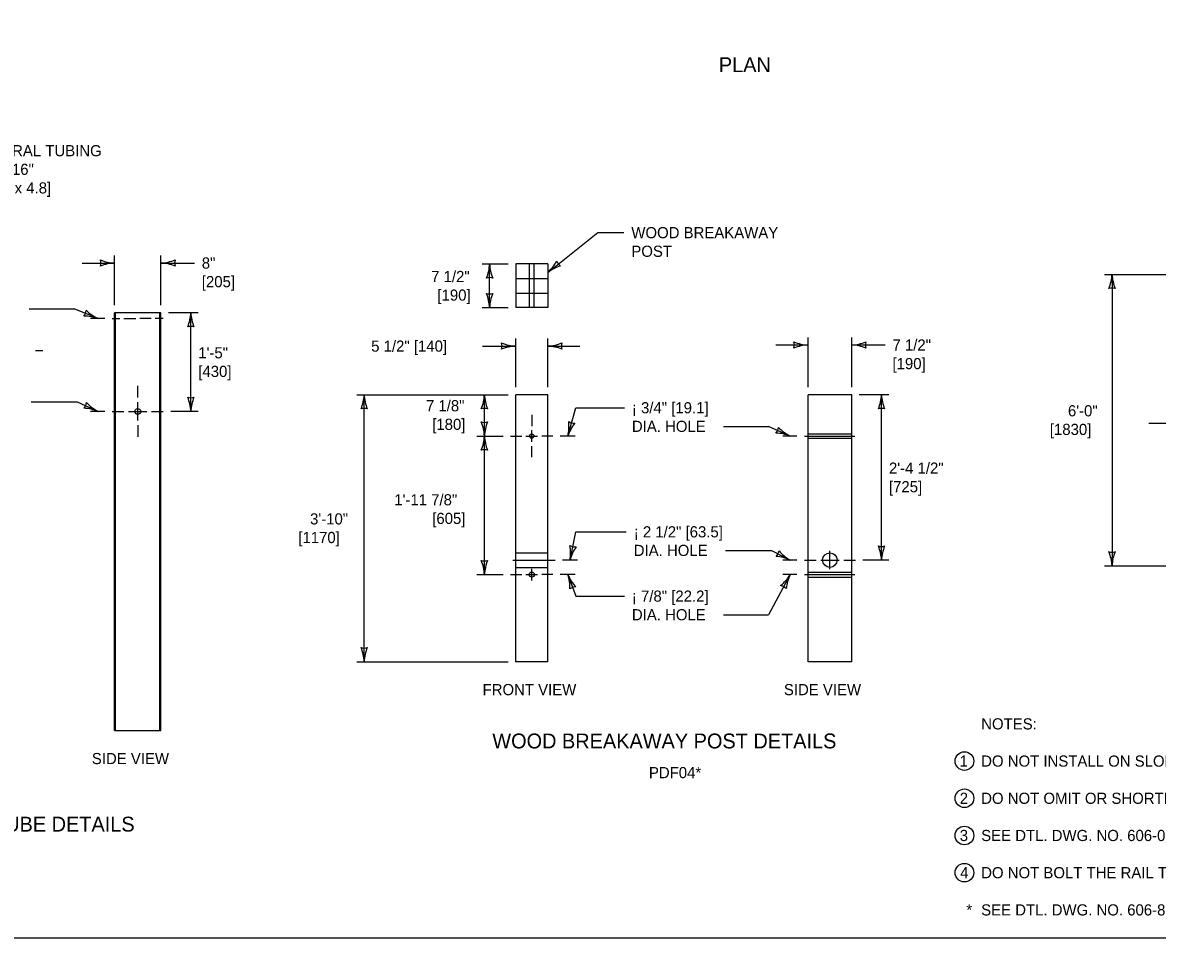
# Model space of a CAD drawing. Extents: x 49991.4 to 50021, y 49987.6 to 50011.4.
# Drawn here: x 50001.79 to 50007.89, y 49987.8 to 49992.72 of the extents above; entities that cross this region are included whole.
import ezdxf

# ---------------------------------------------------------------- set-up
doc = ezdxf.new("R2010")
doc.units = 0
for name, color, linetype in [('Level 1', 7, 'Continuous'), ('Level 2', 7, 'Continuous'), ('Level 3', 7, 'Continuous'), ('Level 4', 7, 'Continuous'), ('Level 5', 7, 'Continuous')]:
    doc.layers.add(name, color=color, linetype=linetype)

msp = doc.modelspace()

# ---------------------------------------------------------------- linework, layer by layer
at = {"layer": 'Level 1'}
for p, q in [((50004.4396, 49991.4237), (50004.4396, 49991.1893)), ((50004.6112, 49991.4237), (50004.4396, 49991.4237)), ((50004.6112, 49991.4237), (50004.6112, 49991.1893)), ((50002.284, 49988.9152), (50002.284, 49991.1616)), ((50002.5336, 49991.1616), (50002.284, 49991.1616)), ((50002.5336, 49988.9152), (50002.5336, 49991.1616)), ((50004.6112, 49991.1893), (50004.4396, 49991.1893)), ((50001.8587, 49990.9595), (50001.8987, 49990.9595)), ((50004.4396, 49989.2858), (50004.4396, 49990.721)), ((50004.6112, 49990.721), (50004.4396, 49990.721)), ((50004.6112, 49989.2858), (50004.6112, 49990.721)), ((50006.0102, 49989.2858), (50006.0102, 49990.721)), ((50006.2446, 49990.721), (50006.0102, 49990.721)), ((50006.2446, 49989.2858), (50006.2446, 49990.721)), ((50007.8408, 49990.5679), (50008.6722, 49990.5679)), ((50004.6112, 49989.2858), (50004.4396, 49989.2858)), ((50006.2446, 49989.2858), (50006.0102, 49989.2858)), ((50002.284, 49988.9152), (50002.5336, 49988.9152))]:
    msp.add_line(p, q, dxfattribs=at)
msp.add_lwpolyline([(49999.3835, 49998.9992), (50016.7501, 49998.9992), (50016.7501, 49987.7988), (49999.3835, 49987.7988)], close=True, dxfattribs=at)
for centre, radius in [((50002.4088, 49990.6312), 0.0156), ((50004.5254, 49990.4987), 0.0117), ((50006.1274, 49989.8318), 0.039), ((50004.5254, 49989.7538), 0.0136)]:
    msp.add_circle(centre, radius, dxfattribs=at)
at = {"layer": 'Level 2'}
for centre in [(50006.8505, 49988.7516), (50006.8505, 49988.5516), (50006.8505, 49988.3516), (50006.8505, 49988.1516)]:
    msp.add_circle(centre, 0.05, dxfattribs=at)
at = {"layer": 'Level 3'}
for p, q in [((50004.6112, 49991.3778), (50004.8814, 49991.5921)), ((50004.8814, 49991.5921), (50005.0208, 49991.5921)), ((50002.284, 49991.2016), (50002.284, 49991.4688)), ((50002.5336, 49991.2016), (50002.5336, 49991.4688)), ((50002.1106, 49991.4288), (50002.284, 49991.4288)), ((50002.5336, 49991.4288), (50002.7128, 49991.4288)), ((50004.2592, 49991.4237), (50004.3996, 49991.4237)), ((50004.2992, 49991.1893), (50004.2992, 49991.4237)), ((50007.6036, 49991.3678), (50008.6322, 49991.3678)), ((50007.6436, 49991.3678), (50007.6436, 49989.8012)), ((50001.8257, 49991.1826), (50002.0669, 49991.1826)), ((50002.1954, 49991.1304), (50002.0669, 49991.1826)), ((50002.2317, 49991.1304), (50002.1554, 49991.1304)), ((50002.734, 49991.1616), (50002.5736, 49991.1616)), ((50002.694, 49990.6312), (50002.694, 49991.1616)), ((50004.2592, 49991.1893), (50004.3996, 49991.1893)), ((50004.4396, 49990.761), (50004.4396, 49991.0223)), ((50004.6112, 49990.761), (50004.6112, 49991.0223)), ((50006.0102, 49990.761), (50006.0102, 49991.0282)), ((50006.2446, 49990.761), (50006.2446, 49991.0282)), ((50004.2614, 49990.9823), (50004.4396, 49990.9823)), ((50004.6112, 49990.9823), (50004.7847, 49990.9823)), ((50005.8368, 49990.9882), (50006.0102, 49990.9882)), ((50006.2446, 49990.9882), (50006.4238, 49990.9882)), ((50003.5853, 49990.721), (50004.3996, 49990.721)), ((50003.6253, 49989.2858), (50003.6253, 49990.721)), ((50004.2713, 49990.4987), (50004.2713, 49990.721)), ((50006.4449, 49990.721), (50006.2846, 49990.721)), ((50006.4049, 49989.8318), (50006.4049, 49990.721)), ((50004.7194, 49990.4987), (50004.763, 49990.6509)), ((50004.763, 49990.6509), (50005.0237, 49990.6509)), ((50002.2317, 49990.6312), (50002.1555, 49990.6312)), ((50002.734, 49990.6312), (50002.586, 49990.6312)), ((50005.5563, 49990.5509), (50005.7974, 49990.5509)), ((50005.914, 49990.4987), (50005.7974, 49990.5509)), ((50004.2313, 49990.4987), (50004.3717, 49990.4987)), ((50004.2713, 49989.7538), (50004.2713, 49990.4987)), ((50004.7594, 49990.4987), (50004.6791, 49990.4987)), ((50005.9503, 49990.4987), (50005.874, 49990.4987)), ((50004.7316, 49989.8318), (50004.763, 49989.984)), ((50004.763, 49989.984), (50005.0337, 49989.984)), ((50004.7716, 49989.8318), (50004.6912, 49989.8318)), ((50005.9503, 49989.8318), (50005.874, 49989.8318)), ((50006.4449, 49989.8318), (50006.3045, 49989.8318)), ((50007.6036, 49989.8012), (50008.6322, 49989.8012)), ((50004.2313, 49989.7538), (50004.3717, 49989.7538)), ((50004.7594, 49989.7538), (50004.6791, 49989.7538)), ((50004.7194, 49989.7538), (50004.763, 49989.6383)), ((50005.914, 49989.7538), (50005.7974, 49989.5383)), ((50005.9503, 49989.7538), (50005.874, 49989.7538)), ((50004.763, 49989.6383), (50005.0237, 49989.6383)), ((50005.5563, 49989.5383), (50005.7974, 49989.5383)), ((50003.5853, 49989.2858), (50004.3996, 49989.2858))]:
    msp.add_line(p, q, dxfattribs=at)
for points in [[(50001.8358, 49990.6834), (50002.083, 49990.6834), (50002.1955, 49990.6312)], [(50005.5663, 49989.884), (50005.8135, 49989.884), (50005.914, 49989.8318)]]:
    msp.add_lwpolyline(points, dxfattribs=at)
for centre, radius, start, end in [((50002.2932, 49991.6509), 0.2223, 247.45601, 267.63952), ((50002.1558, 49991.4288), 0.0548, 342.13882, 17.86118), ((50002.5221, 49991.6615), 0.233, 272.82731, 292.07716), ((50002.6618, 49991.4288), 0.0548, 162.13882, 197.86118), ((50004.4561, 49991.5517), 0.233, 311.72481, 330.97466), ((50004.711, 49991.4583), 0.0548, 201.03631, 236.75867), ((50002.2955, 49991.1961), 0.233, 92.82731, 112.07716), ((50002.5245, 49991.2067), 0.2223, 67.45601, 87.63952), ((50004.0771, 49991.4329), 0.2223, 337.45601, 357.63952), ((50004.5319, 49991.4352), 0.233, 182.82731, 202.07716), ((50004.7436, 49991.1992), 0.2223, 106.35351, 126.53701), ((50004.2992, 49991.2955), 0.0548, 72.13882, 107.86118), ((50007.4214, 49991.377), 0.2223, 337.45601, 357.63952), ((50007.8763, 49991.3793), 0.233, 182.82731, 202.07716), ((50004.2992, 49991.3175), 0.0548, 252.13882, 287.86118), ((50004.0665, 49991.1778), 0.233, 2.82731, 22.07716), ((50004.5213, 49991.1802), 0.2223, 157.45601, 177.63952), ((50007.6436, 49991.2396), 0.0548, 72.13882, 107.86118), ((50002.0766, 49991.1786), 0.0548, 320.03811, 355.76047), ((50002.1203, 49990.9211), 0.2223, 70.25977, 90.44328), ((50002.2936, 49991.3417), 0.233, 225.82213, 245.07198), ((50002.4612, 49991.1731), 0.233, 337.92284, 357.17269), ((50002.9161, 49991.1707), 0.2223, 182.36048, 202.54399), ((50002.694, 49991.0334), 0.0548, 72.13882, 107.86118), ((50004.4488, 49991.2044), 0.2223, 247.45601, 267.63952), ((50004.3114, 49990.9823), 0.0548, 342.13882, 17.86118), ((50004.4511, 49990.7496), 0.233, 92.82731, 112.07716), ((50004.5997, 49991.215), 0.233, 272.82731, 292.07716), ((50004.6021, 49990.7602), 0.2223, 67.45601, 87.63952), ((50004.7394, 49990.9823), 0.0548, 162.13882, 197.86118), ((50006.0194, 49991.2103), 0.2223, 247.45601, 267.63952), ((50005.882, 49990.9882), 0.0548, 342.13882, 17.86118), ((50006.0217, 49990.7555), 0.233, 92.82731, 112.07716), ((50006.2331, 49991.2209), 0.233, 272.82731, 292.07716), ((50006.2355, 49990.7661), 0.2223, 67.45601, 87.63952), ((50006.3728, 49990.9882), 0.0548, 162.13882, 197.86118), ((50002.4718, 49990.622), 0.2223, 2.36048, 22.54399), ((50002.694, 49990.7594), 0.0548, 252.13882, 287.86118), ((50002.9267, 49990.6197), 0.233, 157.92284, 177.17269), ((50003.4032, 49990.7301), 0.2223, 337.45601, 357.63952), ((50003.858, 49990.7325), 0.233, 182.82731, 202.07716), ((50004.0492, 49990.7301), 0.2223, 337.45601, 357.63952), ((50004.504, 49990.7325), 0.233, 182.82731, 202.07716), ((50006.1722, 49990.7325), 0.233, 337.92284, 357.17269), ((50006.6271, 49990.7301), 0.2223, 182.36048, 202.54399), ((50002.0792, 49990.6851), 0.0548, 317.24943, 352.97179), ((50002.108, 49990.4152), 0.233, 67.93792, 87.18777), ((50002.2973, 49990.8288), 0.2223, 222.56662, 242.75013), ((50003.6253, 49990.5928), 0.0548, 72.13882, 107.86118), ((50004.2713, 49990.5928), 0.0548, 72.13882, 107.86118), ((50006.4049, 49990.5928), 0.0548, 72.13882, 107.86118), ((50004.2713, 49990.6269), 0.0548, 252.13882, 287.86118), ((50004.0386, 49990.4872), 0.233, 2.82731, 22.07716), ((50004.4935, 49990.4895), 0.2223, 157.45601, 177.63952), ((50004.4925, 49990.5517), 0.233, 346.84214, 6.09199), ((50004.9304, 49990.4287), 0.2223, 141.47084, 161.65435), ((50004.7547, 49990.6219), 0.0548, 236.15365, 271.87601), ((50005.797, 49990.5511), 0.0548, 318.01665, 353.73901), ((50006.0196, 49990.7064), 0.233, 223.80067, 243.05052), ((50004.0492, 49990.5078), 0.2223, 337.45601, 357.63952), ((50004.504, 49990.5102), 0.233, 182.82731, 202.07716), ((50005.8316, 49990.2922), 0.2223, 68.23831, 88.42182), ((50004.2713, 49990.3705), 0.0548, 72.13882, 107.86118), ((50004.7576, 49989.9573), 0.0548, 240.46023, 276.18259), ((50004.5014, 49989.8676), 0.233, 351.14872, 10.39857), ((50004.9473, 49989.7779), 0.2223, 145.77742, 165.96093), ((50005.8002, 49989.8909), 0.0548, 314.69944, 350.4218), ((50005.817, 49989.62), 0.233, 65.38793, 84.63778), ((50006.0245, 49990.0247), 0.2223, 220.01663, 240.20014), ((50006.1828, 49989.8226), 0.2223, 2.36048, 22.54399), ((50006.4049, 49989.96), 0.0548, 252.13882, 287.86118), ((50006.6376, 49989.8203), 0.233, 157.92284, 177.17269), ((50007.6436, 49989.9294), 0.0548, 252.13882, 287.86118), ((50007.4109, 49989.7897), 0.233, 2.82731, 22.07716), ((50007.8657, 49989.7921), 0.2223, 157.45601, 177.63952), ((50004.2713, 49989.882), 0.0548, 252.13882, 287.86118), ((50004.0386, 49989.7423), 0.233, 2.82731, 22.07716), ((50004.4935, 49989.7446), 0.2223, 157.45601, 177.63952), ((50004.5084, 49989.6839), 0.2223, 358.13456, 18.31807), ((50004.9331, 49989.8467), 0.233, 203.50586, 222.75571), ((50005.7148, 49989.8746), 0.233, 309.51357, 328.76342), ((50006.1137, 49989.6562), 0.2223, 153.95121, 174.13472), ((50004.7647, 49989.6338), 0.0548, 92.81737, 128.53973), ((50005.853, 49989.641), 0.0548, 43.72955, 79.45191), ((50003.6253, 49989.414), 0.0548, 252.13882, 287.86118), ((50003.3926, 49989.2743), 0.233, 2.82731, 22.07716), ((50003.8475, 49989.2766), 0.2223, 157.45601, 177.63952)]:
    msp.add_arc(centre, radius, start, end, dxfattribs=at)
at = {"layer": 'Level 4'}
for p, q in [((50004.5118, 49991.4237), (50004.5118, 49991.1893)), ((50004.5391, 49991.1893), (50004.5391, 49991.4237)), ((50004.4396, 49991.3455), (50004.6112, 49991.3455)), ((50004.4396, 49991.2675), (50004.6112, 49991.2675)), ((50002.284, 49991.1421), (50002.2899, 49991.1421)), ((50002.2899, 49988.9152), (50002.2899, 49991.1616)), ((50002.5278, 49988.9152), (50002.5278, 49991.1616)), ((50002.5278, 49991.1421), (50002.5336, 49991.1421)), ((50002.284, 49991.1187), (50002.2899, 49991.1187)), ((50002.5278, 49991.1187), (50002.5336, 49991.1187)), ((50006.0102, 49990.5104), (50006.2446, 49990.5104)), ((50006.0102, 49990.487), (50006.2446, 49990.487)), ((50004.4396, 49989.8708), (50004.6112, 49989.8708)), ((50004.4396, 49989.7928), (50004.6112, 49989.7928)), ((50006.0102, 49989.7674), (50006.2446, 49989.7674)), ((50006.0102, 49989.7401), (50006.2446, 49989.7401))]:
    msp.add_line(p, q, dxfattribs=at)
at = {"layer": 'Level 5'}
for p, q in [((50002.2717, 49991.1304), (50002.3126, 49991.1304)), ((50002.3348, 49991.1304), (50002.3978, 49991.1304)), ((50002.48, 49991.1304), (50002.4199, 49991.1304)), ((50002.546, 49991.1304), (50002.5021, 49991.1304)), ((50002.4088, 49990.7053), (50002.4088, 49990.7683)), ((50002.4088, 49990.582), (50002.4088, 49990.6803)), ((50002.2717, 49990.6312), (50002.3347, 49990.6312)), ((50002.3597, 49990.6312), (50002.458, 49990.6312)), ((50002.483, 49990.6312), (50002.546, 49990.6312)), ((50004.5254, 49990.6124), (50004.5253, 49990.5524)), ((50002.4088, 49990.557), (50002.4088, 49990.4941)), ((50004.5254, 49990.4672), (50004.5254, 49990.5302)), ((50004.4117, 49990.4987), (50004.4717, 49990.4987)), ((50004.4939, 49990.4987), (50004.5569, 49990.4987)), ((50004.6391, 49990.4987), (50004.579, 49990.4987)), ((50005.9903, 49990.4987), (50006.261, 49990.4987)), ((50004.5254, 49990.385), (50004.5253, 49990.445)), ((50006.1274, 49989.7826), (50006.1274, 49989.8809)), ((50004.4239, 49989.8318), (50004.6512, 49989.8318)), ((50005.9903, 49989.8318), (50006.0533, 49989.8318)), ((50006.0783, 49989.8318), (50006.1766, 49989.8318)), ((50006.2016, 49989.8318), (50006.2645, 49989.8318)), ((50004.4117, 49989.7538), (50004.4717, 49989.7538)), ((50004.4939, 49989.7538), (50004.5569, 49989.7538)), ((50004.5254, 49989.7223), (50004.5254, 49989.7853)), ((50004.6391, 49989.7538), (50004.579, 49989.7538)), ((50005.9903, 49989.7538), (50006.261, 49989.7538))]:
    msp.add_line(p, q, dxfattribs=at)

# ---------------------------------------------------------------- texts
at = {"layer": 'Level 2'}
for s, height, p in [('PLAN', 0.08, (50005.531, 49992.4549)), ('STRUCTURAL TUBING ', 0.06, (50001.3502, 49992.0027)), ('8" x 6" x 3/16"', 0.06, (50001.3502, 49991.9027)), ('[203 x 152 x 4.8]', 0.06, (50001.3502, 49991.8027)), ('WOOD BREAKAWAY', 0.06, (50005.0608, 49991.5621)), ('POST', 0.06, (50005.0608, 49991.4621)), ('8"', 0.06, (50002.7528, 49991.3988)), ('7 1/2"', 0.06, (50003.9851, 49991.3265)), ('[205]', 0.06, (50002.7528, 49991.2988)), ('[190]', 0.06, (50004.0188, 49991.2265)), ('5 1/2" [140]', 0.06, (50003.663, 49990.9523)), ('7 1/2"', 0.06, (50006.4638, 49990.9582)), ('1\'-5"', 0.06, (50002.734, 49990.9164)), ('[190]', 0.06, (50006.4638, 49990.8582)), ('[430]', 0.06, (50002.734, 49990.8164)), ('7 1/8"', 0.06, (50003.9572, 49990.6317)), ('¡ 3/4" [19.1]', 0.06, (50005.0637, 49990.6209)), ('6\'-0"', 0.06, (50007.4066, 49990.6045)), ('[180]', 0.06, (50003.9909, 49990.5317)), ('DIA. HOLE', 0.06, (50005.0637, 49990.5209)), ('[1830]', 0.06, (50007.3093, 49990.5045)), ('2\'-4 1/2"', 0.06, (50006.4449, 49990.2964)), ('[725]', 0.06, (50006.4449, 49990.1964)), ('1\'-11 7/8"', 0.06, (50003.7871, 49990.1262)), ('3\'-10"', 0.06, (50003.3345, 49990.0234)), ('[605]', 0.06, (50003.9909, 49990.0262)), (' [1170]', 0.06, (50003.249, 49989.9234)), ('¡ 2 1/2" [63.5]', 0.06, (50005.0737, 49989.954)), ('DIA. HOLE', 0.06, (50005.0737, 49989.854)), ('¡ 7/8" [22.2]', 0.06, (50005.0637, 49989.6083)), ('DIA. HOLE', 0.06, (50005.0637, 49989.5083)), ('FRONT VIEW', 0.06, (50004.2613, 49989.1058)), ('SIDE VIEW', 0.06, (50005.8804, 49989.1058)), ('NOTES:', 0.06, (50006.9405, 49988.9216)), ('WOOD BREAKAWAY POST DETAILS', 0.08, (50004.3138, 49988.8196)), ('SIDE VIEW', 0.06, (50002.162, 49988.7352)), ('1', 0.06, (50006.8244, 49988.7217)), ('DO NOT INSTALL ON SLOPES STEEPER THAN 2:1.', 0.06, (50006.9405, 49988.7216)), ('PDF04*', 0.06, (50005.1552, 49988.6596)), ('2', 0.06, (50006.8253, 49988.5216)), ('DO NOT OMIT OR SHORTEN ANCHOR SECTION.', 0.06, (50006.9405, 49988.5216)), ('MGS FOUNDATION TUBE DETAILS', 0.08, (50000.6207, 49988.3726)), ('3', 0.06, (50006.8252, 49988.3216)), ('SEE DTL. DWG. NO. 606-05A FOR GUARDRAIL WIDENING REQUIREMENTS.', 0.06, (50006.9405, 49988.3216)), ('4', 0.06, (50006.8277, 49988.1216)), ('DO NOT BOLT THE RAIL TO THE CRT POST LOCATED AT THE CENTER OF THE BENT RAIL.', 0.06, (50006.9405, 49988.1216)), ('*', 0.06, (50006.8607, 49987.9216)), ('SEE DTL. DWG. NO. 606-80 FOR SCHEDULE OF GUARDRAIL HARDWARE.', 0.06, (50006.9405, 49987.9216))]:
    msp.add_text(s, height=height, dxfattribs=at).set_placement(p)

doc.saveas('drawing.dxf')
